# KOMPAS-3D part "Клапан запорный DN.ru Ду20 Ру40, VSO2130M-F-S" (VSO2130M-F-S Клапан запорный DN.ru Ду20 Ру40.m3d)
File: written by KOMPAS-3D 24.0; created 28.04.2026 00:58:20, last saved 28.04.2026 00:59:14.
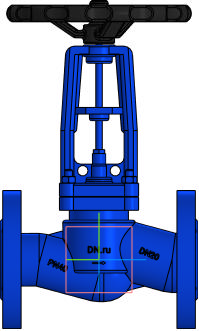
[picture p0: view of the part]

Document properties: Автор: DN.ru; Полное имя файла: C:\Работа\ГОТОВЫЕ ИСХОДНИКИ\VSO2130M-F-S Клапан запорный сильфонный DN.ru Ду15-100 Ру40\DN20\VSO2130M-F-S Клапан запорный DN.ru Ду20 Ру40.m3d

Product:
- Body: Тело 1  | qty 1
    Масса: 5.217639
- Part/product: Клапан запорный DN.ru Ду20 Ру40  | designation VSO2130M-F-S
    Масса: 5
    Раздел спецификации: Прочие изделия
    Примечание: D090-01971

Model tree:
1. Операция без истории:1

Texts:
  VSO2130M-F-S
